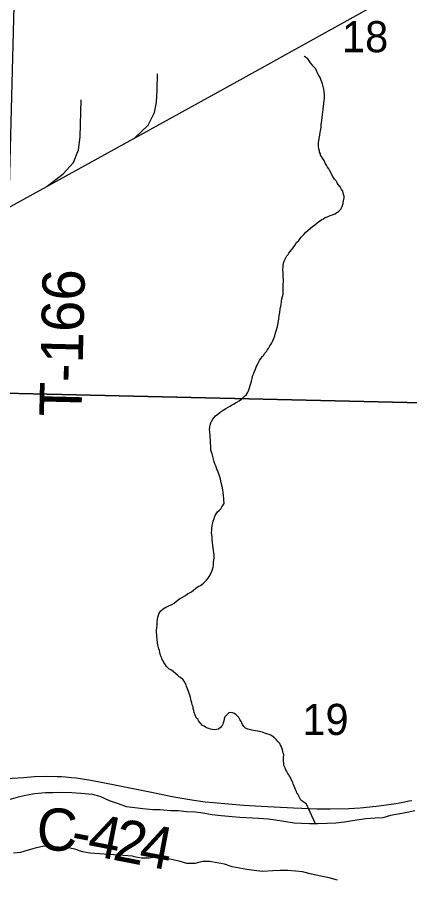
# Model space of a CAD drawing. Extents: x 0 to 34, y 0 to 22.
# Drawn here: x 7.471 to 7.999, y 18.726 to 19.887 of the extents above; entities that cross this region are included whole.
import ezdxf

# ---------------------------------------------------------------- set-up
doc = ezdxf.new("R2010")
doc.units = 0
for name, color, linetype in [('GM_X_County_Road', 7, 'Continuous'), ('GM_X_County_Road_Text', 7, 'Continuous'), ('GM_X_Major_River', 7, 'Continuous'), ('GM_X_Minor_River', 7, 'Continuous'), ('GM_X_Rail_Line', 7, 'Continuous'), ('GM_X_Section', 7, 'Continuous'), ('GM_X_Section_Text', 7, 'Continuous'), ('GM_X_Township_Road_Text', 7, 'Continuous')]:
    doc.layers.add(name, color=color, linetype=linetype)

msp = doc.modelspace()

# ---------------------------------------------------------------- linework, layer by layer
at = {"layer": 'GM_X_County_Road'}
msp.add_line((7.9974, 18.8323), (8.0014, 18.8331), dxfattribs=at)
for points in [[(7.4476, 18.8616), (7.4574, 18.8623), (7.4792, 18.8638), (7.4941, 18.865), (7.5103, 18.8655), (7.5246, 18.8653), (7.5301, 18.8652), (7.5358, 18.8646), (7.5438, 18.8639), (7.5501, 18.8632), (7.5697, 18.8601), (7.6021, 18.8539), (7.649, 18.8445), (7.6813, 18.838), (7.7082, 18.8333), (7.7235, 18.8311)], [(7.7235, 18.8311), (7.7347, 18.83), (7.775, 18.8268), (7.7991, 18.8252), (7.8426, 18.8228), (7.8742, 18.8217), (7.8916, 18.8215), (7.917, 18.8221), (7.9319, 18.8231), (7.9535, 18.8252), (7.9775, 18.8285), (7.9876, 18.8304), (7.9974, 18.8323)]]:
    msp.add_lwpolyline(points, dxfattribs=at)
at = {"layer": 'GM_X_Major_River'}
for points in [[(8.0055, 18.8189), (7.9953, 18.8169), (7.9834, 18.8145), (7.9728, 18.8125), (7.9628, 18.8097), (7.9522, 18.8092), (7.9397, 18.8084), (7.9218, 18.8055), (7.9111, 18.8039), (7.8993, 18.8026), (7.8879, 18.8018), (7.875, 18.8014), (7.864, 18.8013), (7.8531, 18.8019), (7.8432, 18.8026), (7.8293, 18.8048), (7.8183, 18.8063), (7.8085, 18.8077), (7.796, 18.8087), (7.7702, 18.8102), (7.7597, 18.8108), (7.7453, 18.8123), (7.7332, 18.8138), (7.7204, 18.816), (7.7105, 18.817), (7.6984, 18.8177), (7.6875, 18.8188), (7.6768, 18.8191), (7.6632, 18.8202), (7.653, 18.8204), (7.6398, 18.8215), (7.6178, 18.8244), (7.6055, 18.8289), (7.5949, 18.8326), (7.5822, 18.8382), (7.572, 18.8408), (7.5565, 18.8423), (7.5444, 18.8434), (7.5304, 18.8437), (7.5186, 18.8433), (7.5088, 18.8432), (7.4943, 18.842), (7.4841, 18.84), (7.4718, 18.8373), (7.4596, 18.8338)], [(7.5688, 18.7619), (7.5586, 18.764), (7.5484, 18.7673), (7.5375, 18.7695), (7.5269, 18.7702), (7.5171, 18.7708), (7.5065, 18.7714), (7.495, 18.7687), (7.4855, 18.7659), (7.4752, 18.7631), (7.4656, 18.7619)], [(7.6259, 18.7581), (7.5688, 18.7619)], [(7.9014, 18.7259), (7.8905, 18.7288), (7.8792, 18.731), (7.8668, 18.7336), (7.8547, 18.737), (7.8449, 18.738), (7.8347, 18.7386), (7.8244, 18.7389), (7.8146, 18.7384), (7.8009, 18.7372), (7.7896, 18.7387), (7.7797, 18.7401), (7.7699, 18.7418), (7.7601, 18.7436), (7.7496, 18.7473), (7.7398, 18.7491), (7.7296, 18.7509), (7.7201, 18.7507), (7.7098, 18.7479), (7.6988, 18.7482), (7.6887, 18.7512), (7.6785, 18.7537), (7.6581, 18.7573), (7.6482, 18.7552), (7.638, 18.7555), (7.6282, 18.7573), (7.6259, 18.7581)]]:
    msp.add_lwpolyline(points, dxfattribs=at)
at = {"layer": 'GM_X_Minor_River'}
for points in [[(7.8336, 19.5659), (7.8351, 19.5678), (7.8363, 19.5696), (7.8379, 19.5715), (7.8399, 19.5741), (7.8419, 19.5767), (7.8442, 19.58), (7.8466, 19.5838), (7.8494, 19.5867), (7.8513, 19.589), (7.8529, 19.5908), (7.8561, 19.5945), (7.8592, 19.5979), (7.8623, 19.6004), (7.8654, 19.603), (7.8681, 19.6052), (7.8709, 19.6074), (7.8736, 19.61), (7.8763, 19.6122), (7.8786, 19.6136), (7.8806, 19.6147), (7.8829, 19.6158), (7.8852, 19.6176), (7.889, 19.6187), (7.8917, 19.6201), (7.8948, 19.6212), (7.8979, 19.6226), (7.9002, 19.6237), (7.9033, 19.6262), (7.9061, 19.6288), (7.9077, 19.6322), (7.9093, 19.6363), (7.9098, 19.6401), (7.9107, 19.6439), (7.9104, 19.6462), (7.9097, 19.6485), (7.9087, 19.6527), (7.9072, 19.655), (7.9061, 19.6569), (7.905, 19.6589), (7.9025, 19.662), (7.901, 19.6643), (7.8996, 19.6666), (7.8977, 19.669), (7.8963, 19.6713), (7.8948, 19.6732), (7.893, 19.6771), (7.8912, 19.6802), (7.8898, 19.6829), (7.8883, 19.6852), (7.8869, 19.6879), (7.8851, 19.6906), (7.8837, 19.6941), (7.8815, 19.6972), (7.88, 19.6995), (7.8789, 19.7014), (7.8786, 19.7033), (7.8775, 19.7053), (7.8772, 19.7072), (7.8765, 19.7099), (7.8762, 19.7133), (7.8759, 19.7156), (7.876, 19.7179), (7.8764, 19.7205), (7.8769, 19.7239), (7.8778, 19.7281), (7.8783, 19.7322), (7.8792, 19.736), (7.8797, 19.7394), (7.8797, 19.7421), (7.8802, 19.7451), (7.8807, 19.7481), (7.8808, 19.7519), (7.8813, 19.7561), (7.8818, 19.7595), (7.8822, 19.7622), (7.8823, 19.7644), (7.8827, 19.7667), (7.8837, 19.7747), (7.8842, 19.7777), (7.8843, 19.7807), (7.884, 19.7826), (7.8837, 19.7864), (7.883, 19.7903), (7.8824, 19.7937), (7.8814, 19.7975), (7.8803, 19.801), (7.8792, 19.8033), (7.8782, 19.806), (7.8767, 19.8087), (7.8749, 19.8118), (7.8735, 19.8152), (7.8717, 19.8183), (7.8699, 19.8203), (7.8677, 19.823), (7.8651, 19.8257), (7.8618, 19.8308), (7.8588, 19.8328), (7.857, 19.834), (7.8566, 19.8344)], [(7.7473, 19.251), (7.7463, 19.256), (7.7453, 19.2606), (7.7443, 19.2652), (7.7429, 19.2698), (7.7411, 19.2748), (7.7394, 19.279), (7.738, 19.2832), (7.7365, 19.2859), (7.7358, 19.2886), (7.7331, 19.2993), (7.732, 19.3016), (7.7314, 19.3043), (7.731, 19.3066), (7.7311, 19.31), (7.7309, 19.3131), (7.7306, 19.3165), (7.7306, 19.3188), (7.7303, 19.3207), (7.7304, 19.3226), (7.7301, 19.3249), (7.7298, 19.3275), (7.7298, 19.3294), (7.7295, 19.3321), (7.73, 19.3355), (7.7304, 19.3382), (7.7313, 19.3412), (7.7321, 19.3431), (7.7341, 19.346), (7.7357, 19.3483), (7.7376, 19.3505), (7.7407, 19.3527), (7.7439, 19.3553), (7.7477, 19.3582), (7.7516, 19.3604), (7.7547, 19.3622), (7.757, 19.3636), (7.7589, 19.3647), (7.7624, 19.3669), (7.7644, 19.368), (7.7663, 19.3691), (7.7694, 19.3709), (7.7725, 19.3731), (7.776, 19.3764), (7.7791, 19.3793), (7.7807, 19.3816), (7.7815, 19.3834), (7.7824, 19.3857), (7.7849, 19.394), (7.7857, 19.397), (7.7866, 19.4008), (7.7874, 19.4038), (7.7887, 19.4068), (7.7895, 19.4094), (7.7911, 19.4132), (7.7928, 19.4173), (7.7948, 19.4214), (7.7968, 19.4252), (7.7984, 19.4278), (7.8007, 19.4304), (7.8023, 19.4323), (7.8035, 19.4345), (7.8059, 19.4371), (7.8071, 19.439), (7.809, 19.4412), (7.8107, 19.4446), (7.8119, 19.4464), (7.8131, 19.4487), (7.8147, 19.4517), (7.8159, 19.4547), (7.8171, 19.4584), (7.8184, 19.4622), (7.8196, 19.4663), (7.8209, 19.4709), (7.8218, 19.4758), (7.8227, 19.4807), (7.8232, 19.4852), (7.8241, 19.4898), (7.8246, 19.4943), (7.8256, 19.5), (7.8264, 19.5042), (7.8269, 19.5079), (7.8278, 19.511), (7.8283, 19.5144), (7.8284, 19.5174), (7.8285, 19.5208), (7.8286, 19.5242), (7.8287, 19.528), (7.8288, 19.5311), (7.8283, 19.541), (7.8284, 19.544), (7.8281, 19.5463), (7.8281, 19.5482), (7.8285, 19.5501), (7.8286, 19.5535), (7.8291, 19.5554), (7.8295, 19.5573), (7.8303, 19.5595), (7.8312, 19.5614), (7.8324, 19.564), (7.8336, 19.5659)], [(7.7021, 18.9767), (7.7007, 18.9809), (7.6996, 18.9832), (7.6986, 18.9863), (7.6982, 18.9882), (7.6964, 18.9921), (7.6939, 18.9952), (7.6905, 18.9983), (7.6887, 18.9995), (7.6868, 19.0011), (7.6839, 19.0035), (7.6805, 19.0066), (7.6772, 19.0086), (7.6749, 19.0102), (7.6716, 19.0133), (7.6701, 19.0153), (7.668, 19.0187), (7.6669, 19.0207), (7.6658, 19.0226), (7.6651, 19.0245), (7.6644, 19.0264), (7.663, 19.0299), (7.6627, 19.0322), (7.662, 19.0349), (7.6613, 19.0368), (7.661, 19.0387), (7.6602, 19.0406), (7.6599, 19.0425), (7.6596, 19.0445), (7.6593, 19.0464), (7.659, 19.0487), (7.6584, 19.0559), (7.6581, 19.0589), (7.6582, 19.062), (7.6587, 19.0654), (7.6588, 19.0688), (7.6588, 19.0707), (7.6589, 19.0737), (7.6594, 19.0764), (7.6599, 19.0798), (7.6607, 19.0824), (7.6615, 19.0851), (7.6639, 19.088), (7.667, 19.091), (7.6705, 19.0932), (7.6736, 19.0946), (7.6778, 19.0964), (7.6817, 19.0986), (7.6852, 19.1011), (7.6891, 19.1041), (7.6929, 19.1066), (7.6972, 19.1088), (7.6999, 19.111), (7.7026, 19.1124), (7.7053, 19.1138), (7.708, 19.116), (7.7111, 19.1186), (7.7142, 19.1208), (7.7173, 19.1222), (7.7193, 19.1237), (7.7212, 19.1252), (7.7255, 19.1296), (7.7275, 19.1322), (7.7291, 19.1344), (7.7327, 19.1412), (7.7335, 19.1438), (7.7344, 19.1468), (7.7348, 19.1495), (7.735, 19.154), (7.7355, 19.159), (7.7356, 19.1616), (7.7356, 19.1635), (7.7353, 19.1666), (7.7346, 19.1693), (7.7344, 19.1723), (7.7337, 19.1765), (7.7334, 19.1803), (7.7332, 19.1841), (7.7329, 19.1876), (7.7326, 19.1906), (7.7323, 19.1937), (7.7324, 19.1963), (7.7325, 19.199), (7.733, 19.2031), (7.7338, 19.2065), (7.7343, 19.2088), (7.7355, 19.2122), (7.7363, 19.2144), (7.7372, 19.2163), (7.7384, 19.2186), (7.7403, 19.2212), (7.7427, 19.2238), (7.7446, 19.2256), (7.7458, 19.2279), (7.7474, 19.2301), (7.749, 19.2327), (7.7488, 19.2373), (7.7489, 19.2399), (7.7482, 19.2434), (7.7476, 19.2476), (7.7473, 19.251)], [(7.8722, 18.8014), (7.8599, 18.828), (7.8581, 18.8292), (7.8551, 18.8316), (7.8525, 18.8332), (7.8511, 18.8359), (7.8496, 18.8386), (7.8485, 18.8409), (7.8471, 18.8429), (7.8464, 18.8452), (7.8453, 18.8479), (7.8442, 18.8498), (7.8432, 18.8521), (7.8421, 18.8552), (7.8414, 18.8571), (7.8392, 18.861), (7.8382, 18.8637), (7.8371, 18.8656), (7.836, 18.8675), (7.8349, 18.8694), (7.8328, 18.8729), (7.8317, 18.8752), (7.8303, 18.8787), (7.8296, 18.8806), (7.8293, 18.8833), (7.8289, 18.8856), (7.8291, 18.889), (7.8291, 18.8909), (7.8292, 18.8947), (7.8285, 18.8966), (7.8275, 18.9012), (7.8261, 18.9051), (7.825, 18.9074), (7.824, 18.9097), (7.8217, 18.912), (7.8195, 18.9144), (7.817, 18.9171), (7.8151, 18.9187), (7.8117, 18.9207), (7.8099, 18.9215), (7.8065, 18.9227), (7.8046, 18.9232), (7.8027, 18.924), (7.8005, 18.9248), (7.7986, 18.9252), (7.7967, 18.9257), (7.7944, 18.9261), (7.7914, 18.9266), (7.7884, 18.9271), (7.7865, 18.9275), (7.7831, 18.9284), (7.7808, 18.9288), (7.7778, 18.9304), (7.7756, 18.9324), (7.7738, 18.9351), (7.7727, 18.9374), (7.772, 18.9393), (7.7702, 18.942), (7.7688, 18.9447), (7.7651, 18.9483), (7.7632, 18.9498), (7.7602, 18.9507), (7.7575, 18.9511), (7.7553, 18.9508), (7.7529, 18.9482), (7.7502, 18.9457), (7.7493, 18.9426), (7.7485, 18.9396), (7.748, 18.9374), (7.7472, 18.9355), (7.7464, 18.9336), (7.7444, 18.931), (7.7413, 18.9288), (7.7387, 18.9285), (7.7356, 18.9278), (7.7333, 18.9283), (7.7307, 18.9287), (7.7284, 18.9296), (7.7266, 18.9304), (7.7239, 18.9316), (7.7221, 18.9328), (7.7202, 18.934), (7.7169, 18.9375), (7.7147, 18.9402), (7.714, 18.9421), (7.7121, 18.9437), (7.711, 18.9456), (7.7089, 18.9514), (7.7083, 18.9541), (7.7076, 18.9568), (7.7073, 18.9591), (7.7062, 18.9618), (7.7055, 18.9644), (7.7048, 18.9671), (7.7041, 18.9694), (7.7038, 18.9717), (7.7028, 18.9748), (7.7021, 18.9767)]]:
    msp.add_lwpolyline(points, dxfattribs=at)
at = {"layer": 'GM_X_Rail_Line'}
for points in [[(6.8451, 19.2922), (7.7668, 19.8007), (8.4856, 20.1997), (8.9, 20.43)], [(7.6291, 19.7247), (7.6468, 19.7415), (7.6555, 19.7589), (7.6579, 19.7724), (7.6589, 19.7888), (7.6596, 19.8106)], [(7.5111, 19.6596), (7.5325, 19.6763), (7.5464, 19.6915), (7.5533, 19.7083), (7.5555, 19.7258), (7.5568, 19.776)]]:
    msp.add_lwpolyline(points, dxfattribs=at)
at = {"layer": 'GM_X_Section'}
for points in [[(7.4792, 20.3884), (8.425, 20.3637), (8.4018, 19.3591), (7.4533, 19.3812)], [(7.4533, 19.3812), (8.4018, 19.3591), (8.3692, 18.3604), (7.436, 18.3837)]]:
    msp.add_lwpolyline(points, close=True, dxfattribs=at)

# ---------------------------------------------------------------- texts
at = {"layer": 'GM_X_County_Road_Text'}
for s, rotation, p in [('C', 357.4701, (7.4959, 18.7666)), ('4', 348.8401, (7.5632, 18.7604)), ('2', 348.8294, (7.5976, 18.7536)), ('4', 349.3779, (7.6325, 18.7467)), ('-', 349.1157, (7.5404, 18.7648))]:
    msp.add_text(s, height=0.0568, rotation=rotation, dxfattribs=at).set_placement(p)
at = {"layer": 'GM_X_Section_Text'}
for s, p in [('18', (7.9076, 19.8399)), ('19', (7.8543, 18.9211))]:
    msp.add_text(s, height=0.04186, rotation=0, dxfattribs=at).set_placement(p)
at = {"layer": 'GM_X_Township_Road_Text'}
msp.add_text('T-166', height=0.05682, rotation=88.5945, dxfattribs=at).set_placement((7.5571, 19.3489))

doc.saveas('drawing.dxf')
